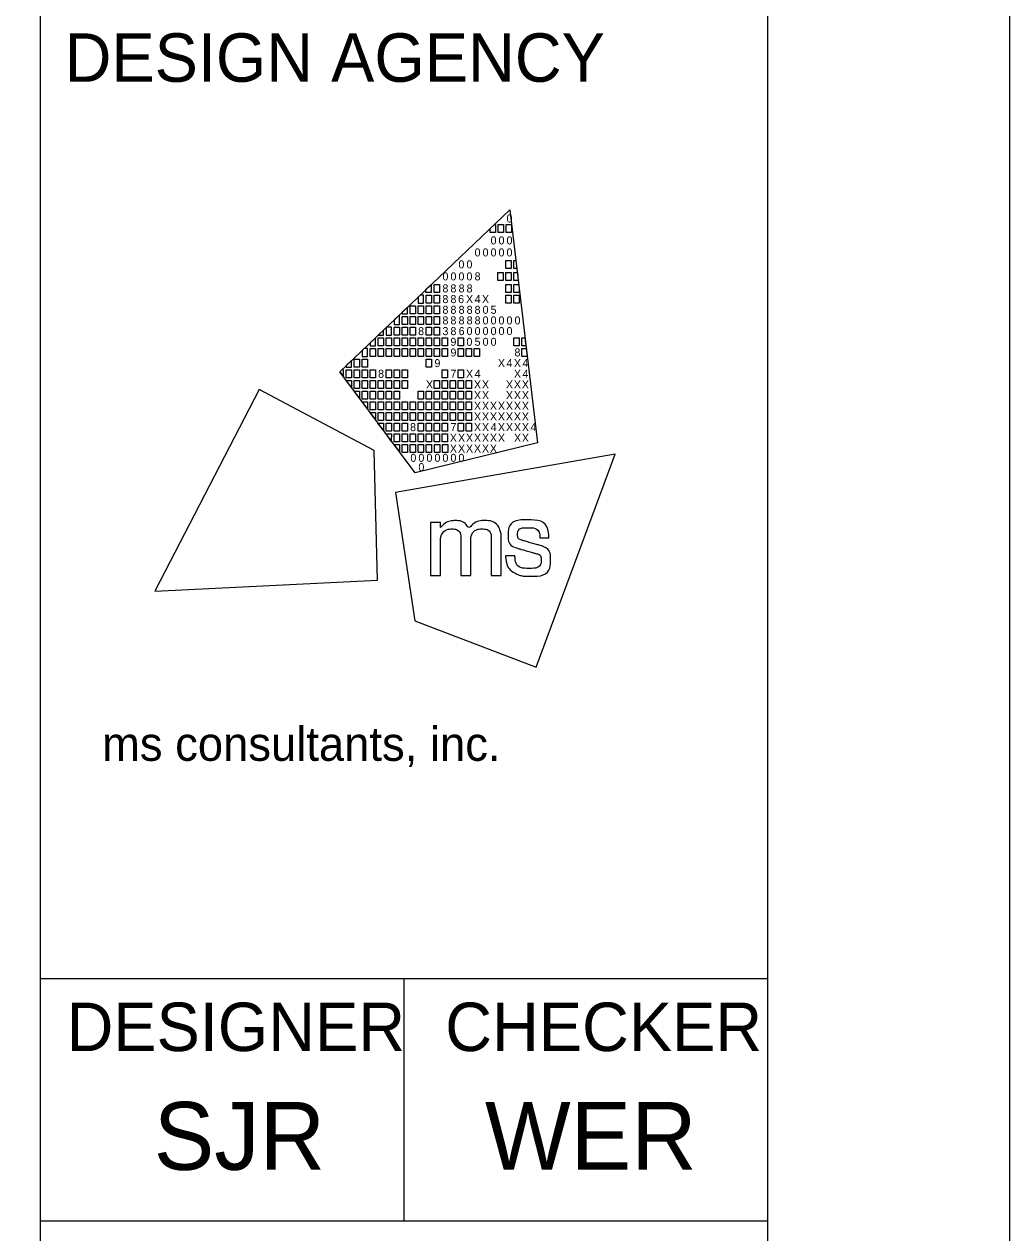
# Model space of a CAD drawing. Extents: x 0 to 34, y 0 to 22.
# Drawn here: x 31.967 to 34, y 2.475 to 4.969 of the extents above; entities that cross this region are included whole.
import ezdxf

# ---------------------------------------------------------------- set-up
doc = ezdxf.new("R2010")
doc.units = 0
for name, color, linetype in [('SH_Border', 7, 'Continuous'), ('SH_Cut_Line', 7, 'Continuous'), ('SH_Data', 7, 'Continuous'), ('SH_Text', 7, 'Continuous')]:
    doc.layers.add(name, color=color, linetype=linetype)

msp = doc.modelspace()

# ---------------------------------------------------------------- linework, layer by layer
at = {"layer": 'SH_Border'}
for p, q in [((32, 0.5), (32, 21.5)), ((32, 3), (33.5, 3)), ((32.75, 3), (32.75, 2.5)), ((32, 2.5), (33.5, 2.5))]:
    msp.add_line(p, q, dxfattribs=at)
msp.add_lwpolyline([(1.5, 21.5), (33.5, 21.5), (33.5, 0.5), (1.5, 0.5)], close=True, dxfattribs=at)
at = {"layer": 'SH_Cut_Line'}
msp.add_lwpolyline([(0, 0), (34, 0), (34, 22), (0, 22)], close=True, dxfattribs=at)
at = {"layer": 'SH_Data'}
msp.add_line((32.75, 4), (32.75, 4), dxfattribs=at)
at = {"layer": 'SH_Text'}
for p, q in [((32.6175, 4.2519), (32.9688, 4.5861)), ((32.9688, 4.5861), (32.9688, 4.5861)), ((32.9688, 4.5861), (33.0253, 4.1052)), ((32.773, 4.043), (32.6175, 4.2519)), ((33.0253, 4.1052), (32.773, 4.043))]:
    msp.add_line(p, q, dxfattribs=at)
for points in [[(32.9279, 4.5472), (32.9369, 4.5558), (32.9389, 4.5558), (32.9389, 4.5393), (32.9279, 4.5393)], [(32.9444, 4.5558), (32.9554, 4.5558), (32.9554, 4.5393), (32.9444, 4.5393)], [(32.9609, 4.5558), (32.9719, 4.5558), (32.9719, 4.5393), (32.9609, 4.5393)], [(32.9606, 4.4815), (32.9716, 4.4815), (32.9716, 4.465), (32.9606, 4.465)], [(32.9771, 4.4815), (32.9811, 4.4815), (32.983, 4.465), (32.9771, 4.465)], [(32.9441, 4.4567), (32.9551, 4.4567), (32.9551, 4.4402), (32.9441, 4.4402)], [(32.9606, 4.4567), (32.9716, 4.4567), (32.9716, 4.4402), (32.9606, 4.4402)], [(32.9771, 4.4567), (32.984, 4.4567), (32.9859, 4.4402), (32.9771, 4.4402)], [(32.7953, 4.4211), (32.8064, 4.4316), (32.8064, 4.4154), (32.7953, 4.4154)], [(32.8123, 4.4319), (32.8233, 4.4319), (32.8233, 4.4154), (32.8123, 4.4154)], [(32.9606, 4.4319), (32.9716, 4.4319), (32.9716, 4.4154), (32.9606, 4.4154)], [(32.9771, 4.4319), (32.9869, 4.4319), (32.9881, 4.4218), (32.9881, 4.4154), (32.9771, 4.4154)], [(32.7958, 4.4099), (32.8068, 4.4099), (32.8068, 4.3934), (32.7958, 4.3934)], [(32.8123, 4.4099), (32.8233, 4.4099), (32.8233, 4.3934), (32.8123, 4.3934)], [(32.9606, 4.4099), (32.9716, 4.4099), (32.9716, 4.3934), (32.9606, 4.3934)], [(32.9771, 4.4099), (32.9881, 4.4099), (32.9881, 4.3934), (32.9771, 4.3934)], [(32.7462, 4.3659), (32.7572, 4.3659), (32.7572, 4.3494), (32.7462, 4.3494)], [(32.7627, 4.3879), (32.7737, 4.3879), (32.7737, 4.3714), (32.7627, 4.3714)], [(32.7627, 4.3659), (32.7737, 4.3659), (32.7737, 4.3494), (32.7627, 4.3494)], [(32.7793, 4.3879), (32.7903, 4.3879), (32.7903, 4.3714), (32.7793, 4.3714)], [(32.7793, 4.3659), (32.7903, 4.3659), (32.7903, 4.3494), (32.7793, 4.3494)], [(32.7958, 4.3879), (32.8068, 4.3879), (32.8068, 4.3714), (32.7958, 4.3714)], [(32.7958, 4.3659), (32.8068, 4.3659), (32.8068, 4.3494), (32.7958, 4.3494)], [(32.8123, 4.3879), (32.8233, 4.3879), (32.8233, 4.3714), (32.8123, 4.3714)], [(32.8123, 4.3659), (32.8233, 4.3659), (32.8233, 4.3494), (32.8123, 4.3494)], [(32.7297, 4.3439), (32.7407, 4.3439), (32.7407, 4.3273), (32.7297, 4.3273)], [(32.7462, 4.3439), (32.7572, 4.3439), (32.7572, 4.3273), (32.7462, 4.3273)], [(32.7627, 4.3439), (32.7737, 4.3439), (32.7737, 4.3273), (32.7627, 4.3273)], [(32.7958, 4.3439), (32.8068, 4.3439), (32.8068, 4.3273), (32.7958, 4.3273)], [(32.8123, 4.3439), (32.8233, 4.3439), (32.8233, 4.3273), (32.8123, 4.3273)], [(32.6967, 4.3218), (32.7077, 4.3218), (32.7077, 4.3053), (32.6967, 4.3053)], [(32.7132, 4.3218), (32.7242, 4.3218), (32.7242, 4.3053), (32.7132, 4.3053)], [(32.7297, 4.3218), (32.7407, 4.3218), (32.7407, 4.3053), (32.7297, 4.3053)], [(32.7462, 4.3218), (32.7572, 4.3218), (32.7572, 4.3053), (32.7462, 4.3053)], [(32.7627, 4.3218), (32.7737, 4.3218), (32.7737, 4.3053), (32.7627, 4.3053)], [(32.7793, 4.3218), (32.7903, 4.3218), (32.7903, 4.3053), (32.7793, 4.3053)], [(32.7958, 4.3218), (32.8068, 4.3218), (32.8068, 4.3053), (32.7958, 4.3053)], [(32.8123, 4.3218), (32.8233, 4.3218), (32.8233, 4.3053), (32.8123, 4.3053)], [(32.8288, 4.3218), (32.8398, 4.3218), (32.8398, 4.3053), (32.8288, 4.3053)], [(32.8618, 4.3218), (32.8728, 4.3218), (32.8728, 4.3053), (32.8618, 4.3053)], [(32.9771, 4.3218), (32.9881, 4.3218), (32.9881, 4.3053), (32.9771, 4.3053)], [(32.9935, 4.3218), (32.9998, 4.3218), (33.0018, 4.3053), (32.9935, 4.3053)], [(32.6802, 4.2998), (32.6912, 4.2998), (32.6912, 4.2833), (32.6802, 4.2833)], [(32.6967, 4.2998), (32.7077, 4.2998), (32.7077, 4.2833), (32.6967, 4.2833)], [(32.7132, 4.2998), (32.7242, 4.2998), (32.7242, 4.2833), (32.7132, 4.2833)], [(32.7297, 4.2998), (32.7407, 4.2998), (32.7407, 4.2833), (32.7297, 4.2833)], [(32.7462, 4.2998), (32.7572, 4.2998), (32.7572, 4.2833), (32.7462, 4.2833)], [(32.7627, 4.2998), (32.7737, 4.2998), (32.7737, 4.2833), (32.7627, 4.2833)], [(32.7793, 4.2998), (32.7903, 4.2998), (32.7903, 4.2833), (32.7793, 4.2833)], [(32.7958, 4.2998), (32.8068, 4.2998), (32.8068, 4.2833), (32.7958, 4.2833)], [(32.8123, 4.2998), (32.8233, 4.2998), (32.8233, 4.2833), (32.8123, 4.2833)], [(32.8288, 4.2998), (32.8398, 4.2998), (32.8398, 4.2833), (32.8288, 4.2833)], [(32.8618, 4.2998), (32.8728, 4.2998), (32.8728, 4.2833), (32.8618, 4.2833)], [(32.8783, 4.2998), (32.8893, 4.2998), (32.8893, 4.2833), (32.8783, 4.2833)], [(32.8947, 4.2998), (32.9057, 4.2998), (32.9057, 4.2833), (32.8947, 4.2833)], [(32.9935, 4.2998), (33.0024, 4.2998), (33.0044, 4.2833), (32.9935, 4.2833)], [(32.6471, 4.2778), (32.6581, 4.2778), (32.6581, 4.2613), (32.6471, 4.2613)], [(32.6637, 4.2778), (32.6747, 4.2778), (32.6747, 4.2613), (32.6637, 4.2613)], [(32.7958, 4.2778), (32.8068, 4.2778), (32.8068, 4.2613), (32.7958, 4.2613)], [(32.6306, 4.2558), (32.6416, 4.2558), (32.6416, 4.2393), (32.6306, 4.2393)], [(32.6471, 4.2558), (32.6581, 4.2558), (32.6581, 4.2393), (32.6471, 4.2393)], [(32.6637, 4.2558), (32.6747, 4.2558), (32.6747, 4.2393), (32.6637, 4.2393)], [(32.6802, 4.2558), (32.6912, 4.2558), (32.6912, 4.2393), (32.6802, 4.2393)], [(32.7132, 4.2558), (32.7242, 4.2558), (32.7242, 4.2393), (32.7132, 4.2393)], [(32.7297, 4.2558), (32.7407, 4.2558), (32.7407, 4.2393), (32.7297, 4.2393)], [(32.7462, 4.2558), (32.7572, 4.2558), (32.7572, 4.2393), (32.7462, 4.2393)], [(32.8288, 4.2558), (32.8398, 4.2558), (32.8398, 4.2393), (32.8288, 4.2393)], [(32.8618, 4.2558), (32.8728, 4.2558), (32.8728, 4.2393), (32.8618, 4.2393)], [(32.6306, 4.2338), (32.6416, 4.2338), (32.6416, 4.22)], [(32.6471, 4.2338), (32.6581, 4.2338), (32.6581, 4.2173), (32.6471, 4.2173)], [(32.6637, 4.2338), (32.6747, 4.2338), (32.6747, 4.2173), (32.6637, 4.2173)], [(32.6802, 4.2338), (32.6912, 4.2338), (32.6912, 4.2173), (32.6802, 4.2173)], [(32.6967, 4.2338), (32.7077, 4.2338), (32.7077, 4.2173), (32.6967, 4.2173)], [(32.7132, 4.2338), (32.7242, 4.2338), (32.7242, 4.2173), (32.7132, 4.2173)], [(32.7297, 4.2338), (32.7407, 4.2338), (32.7407, 4.2173), (32.7297, 4.2173)], [(32.7462, 4.2338), (32.7572, 4.2338), (32.7572, 4.2173), (32.7462, 4.2173)], [(32.8123, 4.2338), (32.8233, 4.2338), (32.8233, 4.2173), (32.8123, 4.2173)], [(32.8288, 4.2338), (32.8398, 4.2338), (32.8398, 4.2173), (32.8288, 4.2173)], [(32.8453, 4.2338), (32.8563, 4.2338), (32.8563, 4.2173), (32.8453, 4.2173)], [(32.8618, 4.2338), (32.8728, 4.2338), (32.8728, 4.2173), (32.8618, 4.2173)], [(32.8783, 4.2338), (32.8893, 4.2338), (32.8893, 4.2173), (32.8783, 4.2173)], [(32.6471, 4.2117), (32.6581, 4.2117), (32.6581, 4.198)], [(32.6637, 4.2117), (32.6747, 4.2117), (32.6747, 4.1952), (32.6637, 4.1952)], [(32.6802, 4.2117), (32.6912, 4.2117), (32.6912, 4.1952), (32.6802, 4.1952)], [(32.6967, 4.2117), (32.7077, 4.2117), (32.7077, 4.1952), (32.6967, 4.1952)], [(32.7132, 4.2117), (32.7242, 4.2117), (32.7242, 4.1952), (32.7132, 4.1952)], [(32.7297, 4.2117), (32.7407, 4.2117), (32.7407, 4.1952), (32.7297, 4.1952)], [(32.7793, 4.2117), (32.7903, 4.2117), (32.7903, 4.1952), (32.7793, 4.1952)], [(32.7958, 4.2117), (32.8068, 4.2117), (32.8068, 4.1952), (32.7958, 4.1952)], [(32.8123, 4.2117), (32.8233, 4.2117), (32.8233, 4.1952), (32.8123, 4.1952)], [(32.8288, 4.2117), (32.8398, 4.2117), (32.8398, 4.1952), (32.8288, 4.1952)], [(32.8453, 4.2117), (32.8563, 4.2117), (32.8563, 4.1952), (32.8453, 4.1952)], [(32.8618, 4.2117), (32.8728, 4.2117), (32.8728, 4.1952), (32.8618, 4.1952)], [(32.8783, 4.2117), (32.8893, 4.2117), (32.8893, 4.1952), (32.8783, 4.1952)], [(32.6637, 4.1897), (32.6747, 4.1897), (32.6747, 4.176)], [(32.6747, 4.1897), (32.6747, 4.1897), (32.6747, 4.1897)], [(32.6802, 4.1897), (32.6912, 4.1897), (32.6912, 4.1732), (32.6802, 4.1732)], [(32.6802, 4.1677), (32.6912, 4.1677), (32.6912, 4.154)], [(32.6967, 4.1897), (32.7077, 4.1897), (32.7077, 4.1732), (32.6967, 4.1732)], [(32.6967, 4.1677), (32.7077, 4.1677), (32.7077, 4.1512), (32.6967, 4.1512)], [(32.7132, 4.1897), (32.7242, 4.1897), (32.7242, 4.1732), (32.7132, 4.1732)], [(32.7132, 4.1677), (32.7242, 4.1677), (32.7242, 4.1512), (32.7132, 4.1512)], [(32.7297, 4.1897), (32.7407, 4.1897), (32.7407, 4.1732), (32.7297, 4.1732)], [(32.7297, 4.1677), (32.7407, 4.1677), (32.7407, 4.1512), (32.7297, 4.1512)], [(32.7462, 4.1897), (32.7572, 4.1897), (32.7572, 4.1732), (32.7462, 4.1732)], [(32.7462, 4.1677), (32.7572, 4.1677), (32.7572, 4.1512), (32.7462, 4.1512)], [(32.7627, 4.1897), (32.7737, 4.1897), (32.7737, 4.1732), (32.7627, 4.1732)], [(32.7627, 4.1677), (32.7737, 4.1677), (32.7737, 4.1512), (32.7627, 4.1512)], [(32.7793, 4.1897), (32.7903, 4.1897), (32.7903, 4.1732), (32.7793, 4.1732)], [(32.7793, 4.1677), (32.7903, 4.1677), (32.7903, 4.1512), (32.7793, 4.1512)], [(32.7958, 4.1897), (32.8068, 4.1897), (32.8068, 4.1732), (32.7958, 4.1732)], [(32.7958, 4.1677), (32.8068, 4.1677), (32.8068, 4.1512), (32.7958, 4.1512)], [(32.8123, 4.1897), (32.8233, 4.1897), (32.8233, 4.1732), (32.8123, 4.1732)], [(32.8123, 4.1677), (32.8233, 4.1677), (32.8233, 4.1512), (32.8123, 4.1512)], [(32.8288, 4.1897), (32.8398, 4.1897), (32.8398, 4.1732), (32.8288, 4.1732)], [(32.8288, 4.1677), (32.8398, 4.1677), (32.8398, 4.1512), (32.8288, 4.1512)], [(32.8453, 4.1897), (32.8563, 4.1897), (32.8563, 4.1732), (32.8453, 4.1732)], [(32.8453, 4.1677), (32.8563, 4.1677), (32.8563, 4.1512), (32.8453, 4.1512)], [(32.8618, 4.1897), (32.8728, 4.1897), (32.8728, 4.1732), (32.8618, 4.1732)], [(32.8618, 4.1677), (32.8728, 4.1677), (32.8728, 4.1512), (32.8618, 4.1512)], [(32.8783, 4.1897), (32.8893, 4.1897), (32.8893, 4.1732), (32.8783, 4.1732)], [(32.8783, 4.1677), (32.8893, 4.1677), (32.8893, 4.1512), (32.8783, 4.1512)], [(32.7077, 4.1305), (32.6965, 4.1457), (32.7077, 4.1457)], [(32.7132, 4.1457), (32.7242, 4.1457), (32.7242, 4.1292), (32.7132, 4.1292)], [(32.7297, 4.1457), (32.7407, 4.1457), (32.7407, 4.1292), (32.7297, 4.1292)], [(32.7462, 4.1457), (32.7572, 4.1457), (32.7572, 4.1292), (32.7462, 4.1292)], [(32.7793, 4.1457), (32.7903, 4.1457), (32.7903, 4.1292), (32.7793, 4.1292)], [(32.7958, 4.1457), (32.8068, 4.1457), (32.8068, 4.1292), (32.7958, 4.1292)], [(32.8123, 4.1457), (32.8233, 4.1457), (32.8233, 4.1292), (32.8123, 4.1292)], [(32.8288, 4.1457), (32.8398, 4.1457), (32.8398, 4.1292), (32.8288, 4.1292)], [(32.8618, 4.1457), (32.8728, 4.1457), (32.8728, 4.1292), (32.8618, 4.1292)], [(32.8783, 4.1457), (32.8893, 4.1457), (32.8893, 4.1292), (32.8783, 4.1292)], [(32.724, 4.1082), (32.7132, 4.1237), (32.7242, 4.1237)], [(32.7297, 4.1237), (32.7407, 4.1237), (32.7407, 4.1072), (32.7297, 4.1072)], [(32.7462, 4.1237), (32.7572, 4.1237), (32.7572, 4.1072), (32.7462, 4.1072)], [(32.7627, 4.1237), (32.7737, 4.1237), (32.7737, 4.1072), (32.7627, 4.1072)], [(32.7793, 4.1237), (32.7903, 4.1237), (32.7903, 4.1072), (32.7793, 4.1072)], [(32.7958, 4.1237), (32.8068, 4.1237), (32.8068, 4.1072), (32.7958, 4.1072)], [(32.8123, 4.1237), (32.8233, 4.1237), (32.8233, 4.1072), (32.8123, 4.1072)], [(32.8288, 4.1237), (32.8398, 4.1237), (32.8398, 4.1072), (32.8288, 4.1072)], [(32.7302, 4.1017), (32.7407, 4.1017), (32.7408, 4.0875)], [(32.7463, 4.1017), (32.7573, 4.1017), (32.7573, 4.0852), (32.7463, 4.0852)], [(32.763, 4.1017), (32.774, 4.1017), (32.774, 4.0852), (32.763, 4.0852)], [(32.7794, 4.1017), (32.7904, 4.1017), (32.7904, 4.0852), (32.7794, 4.0852)], [(32.796, 4.1017), (32.807, 4.1017), (32.807, 4.0852), (32.796, 4.0852)], [(32.8129, 4.1017), (32.8239, 4.1017), (32.8239, 4.0851), (32.8129, 4.0851)], [(32.8296, 4.1017), (32.8406, 4.1017), (32.8406, 4.0851), (32.8296, 4.0851)]]:
    msp.add_lwpolyline(points, close=True, dxfattribs=at)
for points in [[(32.7903, 4.4099), (32.7836, 4.4099), (32.7793, 4.4058), (32.7793, 4.3934), (32.7903, 4.3934), (32.7903, 4.4099)], [(32.7407, 4.3691), (32.7297, 4.3587), (32.7297, 4.3494), (32.7407, 4.3494), (32.7407, 4.3691)], [(32.7572, 4.3849), (32.7462, 4.3744), (32.7462, 4.3714), (32.7572, 4.3714), (32.7572, 4.3849)], [(32.7242, 4.3439), (32.7141, 4.3439), (32.7132, 4.343), (32.7132, 4.3273), (32.7242, 4.3273), (32.7242, 4.3439)], [(32.6912, 4.322), (32.6802, 4.3115), (32.6802, 4.3053), (32.6912, 4.3053), (32.6912, 4.322)], [(32.7077, 4.3377), (32.6968, 4.3273), (32.7077, 4.3273), (32.7077, 4.3377)], [(32.6747, 4.2998), (32.6679, 4.2998), (32.6637, 4.2958), (32.6637, 4.2833), (32.6747, 4.2833), (32.6747, 4.2998)], [(32.6416, 4.2749), (32.6306, 4.2644), (32.6306, 4.2613), (32.6416, 4.2613), (32.6416, 4.2749)], [(32.6251, 4.2558), (32.6216, 4.2558), (32.6175, 4.2519), (32.6251, 4.2417), (32.6251, 4.2558)], [(32.4512, 4.2149), (32.2359, 3.7988), (32.6956, 3.8215), (32.6884, 4.0892), (32.4512, 4.2149)], [(33.0229, 3.6422), (33.1859, 4.0814), (32.7324, 4.0029), (32.7722, 3.7381), (33.0229, 3.6422)]]:
    msp.add_lwpolyline(points, dxfattribs=at)
for points in [[(32.8048, 3.8315), (32.8048, 3.8315), (32.8048, 3.9409), (32.8048, 3.9409), (32.8048, 3.9409), (32.8255, 3.9409), (32.8255, 3.9409), (32.8255, 3.9409), (32.8255, 3.9297), (32.8255, 3.9297), (32.8346, 3.9399), (32.8457, 3.9445), (32.8555, 3.9445), (32.8688, 3.9445), (32.8791, 3.9372), (32.8837, 3.9266), (32.8915, 3.9381), (32.905, 3.9446), (32.9166, 3.9446), (32.9325, 3.9446), (32.9451, 3.935), (32.9494, 3.9213), (32.9494, 3.9212), (32.9494, 3.9212), (32.9494, 3.9212), (32.9501, 3.919), (32.9506, 3.9172), (32.9506, 3.9071), (32.9506, 3.9071), (32.9506, 3.8314), (32.9506, 3.8314), (32.9506, 3.8314), (32.9303, 3.8314), (32.9303, 3.8314), (32.9303, 3.8314), (32.9303, 3.9048), (32.9303, 3.9048), (32.9303, 3.9201), (32.9219, 3.9274), (32.911, 3.9274), (32.8995, 3.9274), (32.8879, 3.9171), (32.8879, 3.9001), (32.8879, 3.9001), (32.8879, 3.8315), (32.8879, 3.8315), (32.8879, 3.8315), (32.8674, 3.8315), (32.8674, 3.8315), (32.8674, 3.8315), (32.8674, 3.9059), (32.8674, 3.9059), (32.8674, 3.9203), (32.8588, 3.9274), (32.8496, 3.9274), (32.8384, 3.9274), (32.8254, 3.917), (32.8254, 3.8962), (32.8254, 3.8962), (32.8254, 3.8315), (32.8254, 3.8315), (32.8254, 3.8315), (32.8048, 3.8315), (32.8048, 3.8315)], [(32.9595, 3.8709), (32.9595, 3.8709), (32.9595, 3.8717), (32.9595, 3.8717), (32.9595, 3.8717), (32.9603, 3.8717), (32.9603, 3.8717), (32.9603, 3.8717), (32.9783, 3.8717), (32.9783, 3.8717), (32.9783, 3.8717), (32.9789, 3.8717), (32.9789, 3.8717), (32.9789, 3.8717), (32.979, 3.871), (32.979, 3.871), (32.9803, 3.8554), (32.9887, 3.846), (33.009, 3.846), (33.0273, 3.846), (33.0333, 3.8554), (33.0333, 3.8631), (33.0333, 3.8732), (33.0256, 3.8758), (33.0175, 3.878), (33.0175, 3.878), (32.987, 3.8867), (32.987, 3.8867), (32.972, 3.8909), (32.9648, 3.9019), (32.9648, 3.9142), (32.9648, 3.9303), (32.9768, 3.9462), (33.0052, 3.9462), (33.0348, 3.9462), (33.0489, 3.9285), (33.0489, 3.9095), (33.0489, 3.9095), (33.0489, 3.9087), (33.0489, 3.9087), (33.0489, 3.9087), (33.0482, 3.9087), (33.0482, 3.9087), (33.0482, 3.9087), (33.0312, 3.9087), (33.0312, 3.9087), (33.0312, 3.9087), (33.0305, 3.9087), (33.0305, 3.9087), (33.0305, 3.9087), (33.0305, 3.9094), (33.0305, 3.9094), (33.0301, 3.9208), (33.0226, 3.93), (33.0056, 3.93), (32.9891, 3.93), (32.9843, 3.9218), (32.9843, 3.9157), (32.9843, 3.9108), (32.9869, 3.9059), (32.9959, 3.9033), (32.9959, 3.9033), (33.0255, 3.8948), (33.0255, 3.8948), (33.0462, 3.8889), (33.0527, 3.8777), (33.0527, 3.8639), (33.0527, 3.8462), (33.041, 3.8298), (33.0087, 3.8298), (32.9952, 3.8298), (32.9877, 3.8321), (32.9823, 3.8348), (32.969, 3.8414), (32.9609, 3.8536), (32.9595, 3.8709)]]:
    msp.add_open_spline(points, degree=3, dxfattribs=at)

# ---------------------------------------------------------------- texts
at = {"layer": 'SH_Border'}
msp.add_text('ms consultants, inc.', height=0.07, rotation=360, dxfattribs=at).set_placement((32.1273, 3.4489))
at = {"layer": 'SH_Data'}
for s, height, p in [('DESIGN AGENCY', 0.1, (32.05, 4.85)), ('DESIGNER', 0.1, (32.054, 2.85)), ('CHECKER', 0.1, (32.8352, 2.85)), ('SJR', 0.14, (32.2339, 2.605)), ('WER', 0.14, (32.9173, 2.605))]:
    msp.add_text(s, height=height, dxfattribs=at).set_placement(p)
at = {"layer": 'SH_Text'}
for s, p in [('0', (32.9617, 4.5597)), ('0', (32.9288, 4.5145)), ('0', (32.9452, 4.5145)), ('0', (32.9617, 4.5145)), ('0', (32.8958, 4.4897)), ('0', (32.9123, 4.4897)), ('0', (32.9288, 4.4897)), ('0', (32.9452, 4.4897)), ('0', (32.9617, 4.4897)), ('0', (32.8625, 4.465)), ('0', (32.879, 4.465)), ('0', (32.8295, 4.4402)), ('0', (32.846, 4.4402)), ('0', (32.8625, 4.4402)), ('0', (32.879, 4.4402)), ('8', (32.8958, 4.4402)), ('8', (32.8295, 4.4154)), ('8', (32.846, 4.4154)), ('8', (32.8628, 4.4154)), ('8', (32.8793, 4.4154)), ('8', (32.8295, 4.3934)), ('8', (32.846, 4.3934)), ('6', (32.8618, 4.3934)), ('X', (32.8781, 4.3934)), ('4', (32.8958, 4.3934)), ('X', (32.911, 4.3934)), ('8', (32.8295, 4.3713)), ('8', (32.8295, 4.3494)), ('8', (32.846, 4.3713)), ('8', (32.846, 4.3494)), ('8', (32.8628, 4.3713)), ('8', (32.8628, 4.3494)), ('8', (32.8794, 4.3713)), ('8', (32.8794, 4.3494)), ('8', (32.8958, 4.3713)), ('8', (32.8958, 4.3494)), ('0', (32.9123, 4.3713)), ('0', (32.9123, 4.3494)), ('5', (32.9287, 4.3713)), ('0', (32.9288, 4.3494)), ('0', (32.9452, 4.3494)), ('0', (32.9617, 4.3494)), ('0', (32.9782, 4.3494)), ('8', (32.7793, 4.3273)), ('3', (32.8295, 4.3273)), ('8', (32.846, 4.3273)), ('6', (32.8629, 4.3273)), ('0', (32.8793, 4.3273)), ('0', (32.8958, 4.3273)), ('0', (32.9123, 4.3273)), ('0', (32.9288, 4.3273)), ('0', (32.9452, 4.3273)), ('0', (32.9617, 4.3273)), ('9', (32.846, 4.3053)), ('0', (32.879, 4.3053)), ('5', (32.8957, 4.3053)), ('0', (32.9123, 4.3053)), ('0', (32.9288, 4.3053)), ('9', (32.846, 4.2833)), ('8', (32.9781, 4.2833)), ('9', (32.813, 4.2613)), ('X', (32.9439, 4.2613)), ('4', (32.9617, 4.2613)), ('X', (32.9769, 4.2613)), ('4', (32.9946, 4.2613)), ('8', (32.6967, 4.2393)), ('7', (32.846, 4.2393)), ('X', (32.8781, 4.2393)), ('4', (32.8958, 4.2393)), ('X', (32.9769, 4.2393)), ('4', (32.9946, 4.2393)), ('X', (32.7955, 4.2173)), ('X', (32.8945, 4.2173)), ('X', (32.911, 4.2173)), ('X', (32.9604, 4.2173)), ('X', (32.9769, 4.2173)), ('X', (32.9933, 4.2173)), ('X', (32.8945, 4.1952)), ('X', (32.911, 4.1952)), ('X', (32.9604, 4.1952)), ('X', (32.9769, 4.1952)), ('X', (32.9933, 4.1952)), ('X', (32.8945, 4.1732)), ('X', (32.8945, 4.1512)), ('X', (32.911, 4.1732)), ('X', (32.911, 4.1512)), ('X', (32.9274, 4.1732)), ('X', (32.9274, 4.1512)), ('X', (32.9439, 4.1732)), ('X', (32.9439, 4.1512)), ('X', (32.9604, 4.1732)), ('X', (32.9604, 4.1512)), ('X', (32.9769, 4.1732)), ('X', (32.9769, 4.1512)), ('X', (32.9933, 4.1732)), ('X', (32.9933, 4.1512)), ('8', (32.7627, 4.1292)), ('7', (32.846, 4.1292)), ('X', (32.8945, 4.1292)), ('X', (32.911, 4.1292)), ('4', (32.9288, 4.1292)), ('X', (32.9439, 4.1292)), ('X', (32.9604, 4.1292)), ('X', (32.9769, 4.1292)), ('X', (32.9933, 4.1292)), ('4', (33.0111, 4.1292)), ('X', (32.8447, 4.1072)), ('X', (32.8616, 4.1072)), ('X', (32.878, 4.1072)), ('X', (32.8945, 4.1072)), ('X', (32.911, 4.1072)), ('X', (32.9274, 4.1072)), ('X', (32.9439, 4.1072)), ('X', (32.9771, 4.1072)), ('X', (32.9933, 4.1072)), ('X', (32.8447, 4.0851)), ('X', (32.8616, 4.0851)), ('X', (32.878, 4.0851)), ('X', (32.8945, 4.0851)), ('X', (32.911, 4.0851)), ('X', (32.9274, 4.0851)), ('0', (32.7634, 4.0659)), ('0', (32.7799, 4.0659)), ('0', (32.7965, 4.0659)), ('0', (32.813, 4.0659)), ('0', (32.8295, 4.0659)), ('0', (32.846, 4.0659)), ('0', (32.8625, 4.0659)), ('0', (32.7799, 4.0467))]:
    msp.add_text(s, height=0.0165, rotation=360, dxfattribs=at).set_placement(p)

doc.saveas('drawing.dxf')
